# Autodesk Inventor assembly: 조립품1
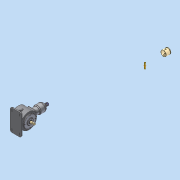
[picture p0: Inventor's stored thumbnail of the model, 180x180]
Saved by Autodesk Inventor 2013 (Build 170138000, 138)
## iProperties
Created: 2015-06
Part Number: 조립품1
Document SubType Name: Assembly
Designer: dgall
Author: dgall
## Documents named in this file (15)
- C:\Users\dgall\Desktop\450605V1036\조립품1.iam
- C:\Users\dgall\Desktop\450605V1036\본체.ipt
- C:\Users\dgall\Desktop\450605V1036\M4x0.7.ipt
- C:\Users\dgall\Desktop\450605V1036\M5x0.8.ipt
- C:\Users\dgall\Desktop\450605V1036\메인 크랭크 축-구동부.ipt
- C:\Users\dgall\Desktop\450605V1036\메인커버.ipt
- C:\Users\dgall\Desktop\450605V1036\베어링 6204.ipt
- C:\Users\dgall\Desktop\450605V1036\베어링 NA 4902.ipt
- C:\Users\dgall\Desktop\450605V1036\실린더.ipt
- C:\Users\dgall\Desktop\450605V1036\실린더헤드.ipt
- C:\Users\dgall\Desktop\450605V1036\오일실.ipt
- C:\Users\dgall\Desktop\450605V1036\커넥팅 로드.ipt
- C:\Users\dgall\Desktop\450605V1036\크랭크 서브축.ipt
- C:\Users\dgall\Desktop\450605V1036\피스톤 핀.ipt
- C:\Users\dgall\Desktop\450605V1036\피스톤.ipt
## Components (14 placed, 4 different names)
1. 피스톤 핀:1
2. 피스톤:1
3. M5x0.8:1
4. M5x0.8:2
5. M5x0.8:3
6. M5x0.8:4
7. M4x0.7:5
8. M4x0.7:6
9. M4x0.7:7
10. M4x0.7:8
11. M4x0.7:1
12. M4x0.7:9
13. M4x0.7:10
14. M4x0.7:11
